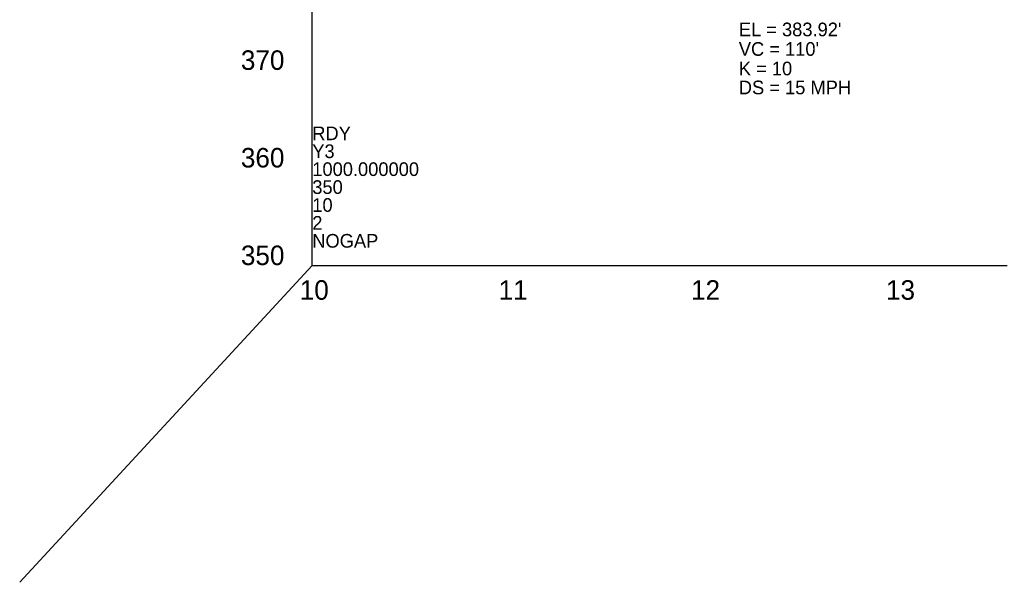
# Model space of a CAD drawing. Extents: x 1625686 to 1640492, y 1161393 to 1175642.
# Drawn here: x 1630056 to 1630562, y 1164578 to 1164867 of the extents above; entities that cross this region are included whole.
import ezdxf

# ---------------------------------------------------------------- set-up
doc = ezdxf.new("R2010")
doc.units = 0
for name, color, linetype in [('Exist Profile Cell', 7, 'Continuous'), ('Exist Vertical Profile Horizontal Axis Label Major', 7, 'Continuous'), ('Exist Vertical Profile Vertical Axis Label', 7, 'Continuous'), ('Prop Vertical Profile Curve Label', 7, 'Continuous'), ('Prop VPI Label', 7, 'Continuous'), ('Scratch_Level_3', 7, 'Continuous')]:
    doc.layers.add(name, color=color, linetype=linetype)

msp = doc.modelspace()

# ---------------------------------------------------------------- linework, layer by layer
at = {"layer": 'Exist Profile Cell'}
for q in [(1630206.28, 1165240.67), (1630562.19, 1164740.67), (1630206.28, 1164740.67)]:
    msp.add_line((1630206.28, 1164740.67), q, dxfattribs=at)
at = {"layer": 'Scratch_Level_3'}
msp.add_line((1630206.28, 1164740.67), (1630056.47, 1164578.44), dxfattribs=at)

# ---------------------------------------------------------------- texts
at = {"layer": 'Exist Profile Cell'}
for s, p in [('RDY', (1630206.28, 1164804.91)), ('Y3', (1630206.28, 1164795.73)), ('1000.000000', (1630206.28, 1164786.56)), ('350', (1630206.28, 1164777.38)), ('10', (1630206.28, 1164768.2)), ('2', (1630206.28, 1164759.03)), ('NOGAP', (1630206.28, 1164749.85))]:
    msp.add_text(s, height=7, dxfattribs=at).set_placement(p)
at = {"layer": 'Exist Vertical Profile Horizontal Axis Label Major'}
for s, p in [('10', (1630199.86, 1164723.17)), ('11', (1630301.7, 1164723.17)), ('12', (1630400.25, 1164723.17)), ('13', (1630500.08, 1164723.17))]:
    msp.add_text(s, height=10, dxfattribs=at).set_placement(p)
at = {"layer": 'Exist Vertical Profile Vertical Axis Label'}
for s, p in [('370', (1630169.71, 1164840.92)), ('360', (1630169.71, 1164790.92)), ('350', (1630169.71, 1164740.92))]:
    msp.add_text(s, height=10, dxfattribs=at).set_placement(p)
at = {"layer": 'Prop Vertical Profile Curve Label'}
for s, p in [("VC = 110'", (1630424.72, 1164848.13)), ('K = 10', (1630424.72, 1164838.13)), ('DS = 15 MPH', (1630424.72, 1164828.41))]:
    msp.add_text(s, height=7, dxfattribs=at).set_placement(p)
at = {"layer": 'Prop VPI Label'}
msp.add_text("EL = 383.92'", height=7, dxfattribs=at).set_placement((1630424.72, 1164858.13))

doc.saveas('drawing.dxf')
